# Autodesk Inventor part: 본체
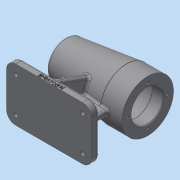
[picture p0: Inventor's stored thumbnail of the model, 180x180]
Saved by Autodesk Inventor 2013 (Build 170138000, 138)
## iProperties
Created: 2018-09
Part Number: 본체
Material: 일반
Document SubType Name: Modeling
Designer: dgall
Density: 1 g/cm^3
Mass: 271.389 g
Surface Area: 663.621 cm^2
Volume: 271.389 cm^3
Author: dgall
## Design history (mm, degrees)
sketch "스케치1"
  geometry: L1 (0, 0)-(112, 0); L2 (112, 21)-(112, 34); L3 (112, 34)-(84, 34); L4 (84, 34)-(3.73, 24.144); L5 (112, 21)-(97, 21); L6 (97, 21)-(97, 24); L7 (97, 24)-(43, 24); L8 (43, 24)-(43, 21); L9 (43, 21)-(31, 21); L10 (31, 21)-(31, 17.5); L11 (31, 17.5)-(13, 17.5); L12 (13, 17.5)-(13, 16); L13 (13, 16)-(9, 16); L14 (9, 16)-(9, 10.5); L15 (9, 10.5)-(6, 10.5); L16 (6, 10.5)-(6, 0); A1 r 80 centre (80, 0) between (3.73, 24.144) and (0, 0)
  constraints: 32 end point, 9 parallel, 5 perpendicular, 2 point on circle, 2 point on line, 1 centre point, 1 horizontal, 1 vertical alignment
  dimensions: "d0" = 68 diameter of L3 L1; "d2" = 7 deg angle of L4 L3; "d4" = 80 radius of A1; "d5" = 28 distance of L2.end L3.end; "d6" = 112 distance of L1.start L1.end; "d7" = 42 diameter of L5 L1; "d8" = 48 diameter of L7 L1; "d9" = 42 diameter of L9 L1; "d10" = 35 diameter of L11 L1; "d11" = 32 diameter of L13 L1; "d12" = 21 diameter of L15 L1; "d13" = 15 distance of L2.start L5.end; "d14" = 54 distance of L6.end L7.end; "d15" = 3 distance of L14.end L15.end; "d16" = 4 distance of L12.end L13.end; "d17" = 18 distance of L10.end L11.end; "d18" = 12 distance of L8.end L9.end
revolve "회전1" sketch "스케치1" stored, may be unused: angle "d19" = 90 deg
fillet "모깎기1" dims "d20" = 3
node "작업축1"
node "작업 평면1"
sketch "스케치2"
  geometry: L1 (-112, 34)-(-112, -34) reference; L2 (-5.669, -24.382)-(-5.669, 24.382) reference; L3 (-83.818, 33.978)-(-83.818, -33.978) reference; L4 (-112, -35)-(0, -35); L5 (0, -35)-(0, 35); L6 (0, 35)-(-112, 35); L7 (-112, 35)-(-112, -35); 4 further points
  constraints: 8 end point, 3 midpoint, 2 parallel, 1 coincident, 1 horizontal, 1 horizontal alignment, 1 perpendicular
  dimensions: "d22" = 112 distance of L4.start L4.end; "d24" = 70 distance of L6.end L4.start
extrude "돌출1" join sketch "스케치2" distance "d25" = 10; taper "d26" = 0 deg
node "작업 평면2"
fillet "모깎기2" dims "d27" = 12
fillet "모깎기3" dims "d28" = 3
sketch "스케치3"
  geometry: L1 (70, 7)-(70, 0) reference; L2 (70, 0)-(0, 0) reference; L3 (0, 0)-(0, 7) reference; L4 (3, 10)-(67, 10) reference; L5 (20.744, 64.524)-(0.181, 8.026); L6 (20.744, 64.524)-(49.256, 64.524); L7 (49.256, 64.524)-(69.819, 8.026); C1 r 30.562 at (35, 74) reference; C2 r 24 at (35, 74) reference; A1 r 3 centre (67, 7) between (70, 7) and (67, 10) reference; A2 r 3 centre (3, 7) between (3, 10) and (0, 7) reference; 1 further point
  constraints: 6 end point, 2 point on circle, 2 tangent, 1 equal length, 1 parallel
  dimensions: "d29" = 20 deg angle of L1 L7; "d30" = 64.52386 distance between parallel lines of L2 L6
extrude "돌출2" join sketch "스케치3" stored distance "d31" = 8; taper "d32" = 0 deg
node "작업 평면3"
sketch "스케치4"
  geometry: L1 (14, -67)-(14, -74) reference; L2 (14, -74)-(-98, -74) reference; L3 (-98, -74)-(-98, -67) reference; L4 (-95, -64)-(-46, -64) reference; L5 (-46, -64)-(-46, -30.071) reference; L6 (-46, -30.071)-(-92.331, -24.382) reference; L7 (-92.331, 24.382)-(-14.182, 33.978) reference; L8 (-13.817, 34)-(14, 34) reference; L9 (14, 34)-(14, 21) reference; L10 (14, 21)-(-1, 21) reference; L11 (-1, 21)-(-1, 24) reference; L12 (-1, 24)-(-55, 24) reference; L13 (-55, 24)-(-55, 21) reference; L14 (-55, 21)-(-67, 21) reference; L15 (-67, 21)-(-67, 17.5) reference; L16 (-67, 17.5)-(-85, 17.5) reference; L17 (-85, 17.5)-(-85, 16) reference; L18 (-85, 16)-(-89, 16) reference; L19 (-89, 16)-(-89, 10.5) reference; L20 (-89, 10.5)-(-92, 10.5) reference; L21 (-92, 10.5)-(-92, -10.5) reference; L22 (-92, -10.5)-(-89, -10.5) reference; L23 (-89, -10.5)-(-89, -16) reference; L24 (-89, -16)-(-85, -16) reference; L25 (-85, -16)-(-85, -17.5) reference; L26 (-85, -17.5)-(-67, -17.5) reference; L27 (-67, -17.5)-(-67, -21) reference; L28 (-67, -21)-(-55, -21) reference; L29 (-55, -21)-(-55, -24) reference; L30 (-55, -24)-(-46, -24) reference; L31 (-46, -24)-(-46, -9.476) reference; L32 (-46, -9.476)-(-38, -9.476) reference; L33 (-38, -9.476)-(-38, -24) reference; L34 (-38, -24)-(-1, -24) reference; L35 (-1, -24)-(-1, -21) reference; L36 (-1, -21)-(14, -21) reference; L37 (14, -21)-(14, -34) reference; L38 (14, -34)-(-13.817, -34) reference; L39 (-14.182, -33.978)-(-38, -31.053) reference; L40 (-38, -31.053)-(-38, -64) reference; L41 (-38, -64)-(11, -64) reference; L42 (14, -21)-(14, 21) reference; L43 (-92, 0)-(14, 0); L44 (14, 0)-(14, 21); L45 (14, 21)-(-1, 21); L46 (-1, 21)-(-1, 24); L47 (-1, 24)-(-55, 24); L48 (-55, 24)-(-55, 21); L49 (-55, 21)-(-67, 21); L50 (-67, 21)-(-67, 17.5); L51 (-67, 17.5)-(-85, 17.5); L52 (-85, 17.5)-(-85, 16); L53 (-85, 16)-(-89, 16); L54 (-89, 16)-(-89, 10.5); L55 (-89, 10.5)-(-92, 10.5); L56 (-92, 10.5)-(-92, 0); L57 (-121.27, 0)-(37.27, 0) reference; A1 r 3 centre (11, -67) between (14, -67) and (11, -64) reference; A2 r 3 centre (-95, -67) between (-95, -64) and (-98, -67) reference; A3 r 3 centre (-91.965, -21.405) between (-94.847, -22.238) and (-92.331, -24.382) reference; A4 r 80 centre (-18, 0) between (-94.847, 22.238) and (-94.847, -22.238) reference; A5 r 3 centre (-91.965, 21.405) between (-92.331, 24.382) and (-94.847, 22.238) reference; A6 r 3 centre (-13.817, 31) between (-13.817, 34) and (-14.182, 33.978) reference; A7 r 3 centre (-13.817, -31) between (-14.182, -33.978) and (-13.817, -34) reference; 1 further point
  constraints: 28 end point, 7 collinear, 6 perpendicular, 2 midpoint
  node "절단 모서리 투영2"
revolve "회전2" stored, may be unused: angle "d34" = 90 deg
sketch "스케치5"
  geometry: L1 (14, -67)-(14, -74) reference; L2 (14, -74)-(-98, -74) reference; L3 (-98, -74)-(-98, -67) reference; L4 (-95, -64)-(-46, -64) reference; L5 (-46, -64)-(-46, -30.071) reference; L6 (-46, -30.071)-(-92.331, -24.382) reference; L7 (-92.331, 24.382)-(-14.182, 33.978) reference; L8 (-13.817, 34)-(14, 34) reference; L9 (14, 34)-(14, 21) reference; L10 (14, 21)-(-1, 21) reference; L11 (-1, 21)-(-1, 24) reference; L12 (-1, 24)-(-55, 24) reference; L13 (-55, 24)-(-55, 21) reference; L14 (-55, 21)-(-67, 21) reference; L15 (-67, 21)-(-67, 17.5) reference; L16 (-67, 17.5)-(-85, 17.5) reference; L17 (-85, 17.5)-(-85, 16) reference; L18 (-85, 16)-(-89, 16) reference; L19 (-89, 16)-(-89, 10.5) reference; L20 (-89, 10.5)-(-92, 10.5) reference; L21 (-92, 10.5)-(-92, -10.5) reference; L22 (-92, -10.5)-(-89, -10.5) reference; L23 (-89, -10.5)-(-89, -16) reference; L24 (-89, -16)-(-85, -16) reference; L25 (-85, -16)-(-85, -17.5) reference; L26 (-85, -17.5)-(-67, -17.5) reference; L27 (-67, -17.5)-(-67, -21) reference; L28 (-67, -21)-(-55, -21) reference; L29 (-55, -21)-(-55, -24) reference; L30 (-55, -24)-(-1, -24) reference; L31 (-1, -24)-(-1, -21) reference; L32 (-1, -21)-(14, -21) reference; L33 (14, -21)-(14, -34) reference; L34 (14, -34)-(-13.817, -34) reference; L35 (-14.182, -33.978)-(-38, -31.053) reference; L36 (-38, -31.053)-(-38, -64) reference; L37 (-38, -64)-(11, -64) reference; L38 (-80, -64)-(-65.334, -9.267); L39 (-65.334, -9.267)-(-4, -9.267); L40 (-4, -9.267)-(-4, -64); L41 (-4, -64)-(-80, -64); A1 r 3 centre (11, -67) between (14, -67) and (11, -64) reference; A2 r 3 centre (-95, -67) between (-95, -64) and (-98, -67) reference; A3 r 3 centre (-91.965, -21.405) between (-94.847, -22.238) and (-92.331, -24.382) reference; A4 r 80 centre (-18, 0) between (-94.847, 22.238) and (-94.847, -22.238) reference; A5 r 3 centre (-91.965, 21.405) between (-92.331, 24.382) and (-94.847, 22.238) reference; A6 r 3 centre (-13.817, 31) between (-13.817, 34) and (-14.182, 33.978) reference; A7 r 3 centre (-13.817, -31) between (-14.182, -33.978) and (-13.817, -34) reference; 1 further point
  constraints: 8 end point, 2 point on line, 1 collinear, 1 parallel, 1 perpendicular
  dimensions: "d35" = 105 deg angle of L4 L38; "d36" = 18 horizontal distance of L2.end L38.start; "d37" = 18 horizontal distance of L1.end L40.end; "d38" = 64.73273 distance between parallel lines of L2 L39
extrude "돌출3" join sketch "스케치5" stored distance "d39" = 8; taper "d40" = 0 deg
revolve "회전3" stored, may be unused: angle "d41" = 90 deg
fillet "모깎기4" dims "d42" = 3
fillet "모깎기5" dims "d43" = 3
fillet "모깎기6" dims "d44" = 3
fillet "모깎기7" dims "d45" = 3
fillet "모깎기8" dims "d46" = 0.3
fillet "모깎기9" dims "d47" = 3
chamfer "모따기1" distance "d48" = 1; stored, may be unused: second distance "d49" = 2, angle "d50" = 45 deg
sketch "스케치6"
  geometry: L1 (0, 23)-(0, -23) reference; L2 (100, 35)-(12, 35) reference; L3 (112, -23)-(112, 23) reference; L4 (12, -35)-(100, -35) reference; A1 r 12 centre (12, -23) between (0, -23) and (12, -35) reference; A2 r 12 centre (12, 23) between (12, 35) and (0, 23) reference; A3 r 12 centre (100, 23) between (112, 23) and (100, 35) reference; A4 r 12 centre (100, -23) between (100, -35) and (112, -23) reference; 5 further points
  constraints: 4 coincident
hole "구멍1" sketch "스케치6" at (100, 23), (100, -23), (12, 23), (12, -23) diameter "d51" = 5.5; stored, may be unused: countersink angle "d55" = 90 deg, drill point angle "d57" = 118 deg; dims "d52" = 6, "d53" = 9.5, "d54" = 5.4, "d56" = 8
sketch "스케치7" dims "d58" = 52
  geometry: C1 r 34 at (0, 0) reference; C2 r 22 at (0, 0) reference; 2 further points
  constraints: 2 vertical alignment, 1 coincident, 2 other
hole "구멍2" sketch "스케치7" at (0, 26) diameter "d59" = 3.242; stored, may be unused: countersink angle "d63" = 90 deg, drill point angle "d65" = 118 deg; dims "d60" = 8, "d61" = 9.5, "d62" = 5.4, "d64" = 11
node "작업 평면4"
sketch "스케치8"
  geometry: L1 (0, 0)-(88, 0) reference; L2 (0, 7)-(88, 7) reference; L3 (100, 0)-(100, 7) reference; 2 further points
  constraints: 1 other
  dimensions: "d70" = 56 distance from line of L3 point (44, 3); "d71" = 3 distance from line of L1 point (44, 3)
feature "엠보싱1" sketch "스케치8" dims "d0" = 68, "d2" = 7 deg, "d4" = 80, "d5" = 28, "d6" = 112, "d7" = 42, "d8" = 48, "d9" = 42, "d10" = 35, "d11" = 32, "d12" = 21, "d13" = 15, "d14" = 54, "d15" = 3, "d16" = 4, "d17" = 18, "d18" = 12, "d72" = 0.5, "d73" = 0
node "솔리드1"
pattern_circular "원형 패턴1" dims angle "d67" = 360 deg
node "투영된 루프1"
node "투영된 루프2"
node "절단 모서리 투영1"
node "절단 모서리 투영3"
other parameters: "d21" = -74, "d33" = 0, "d69" = 87.5
